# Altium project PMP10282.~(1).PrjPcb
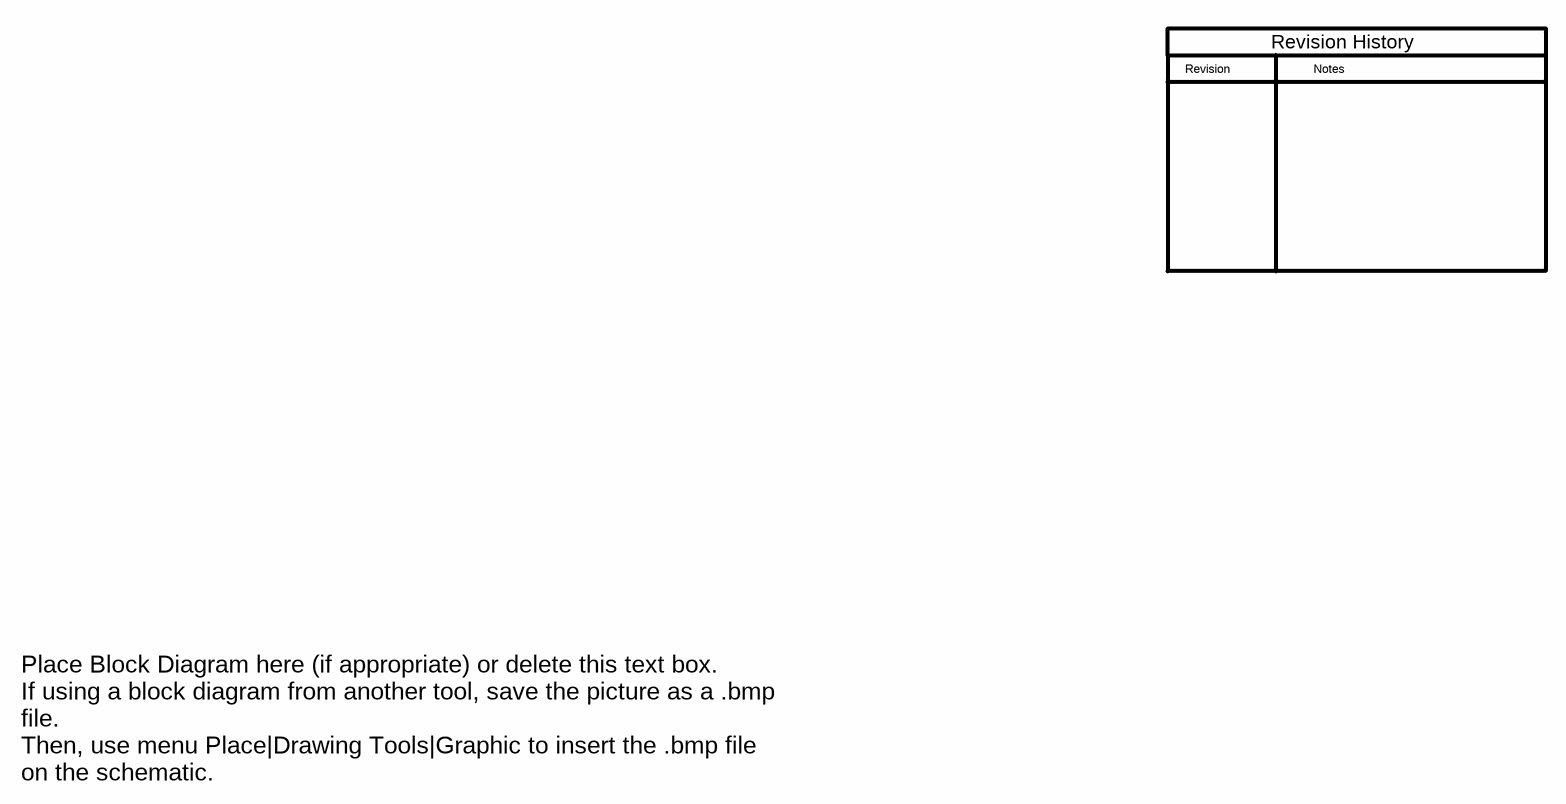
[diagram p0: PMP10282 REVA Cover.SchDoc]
CopyrightYear: 2014; PCB_Layout: Who did the Layout?; PCB_Rev: E1; PRJ_Customer: Public Release; PRJ_Engineer: Enter name of project lead; PRJ_Number: XX####; PRJ_Title: Change in menu Project|Project Options|Parameters; SCH_Rev: E1; TechSupport: http://www.ti.com/support
3 sheets, 79 parts. Net scope: global (net labels, ports and power ports of the same name join across sheets).
Board file: PMP10282 REVA.PcbDoc
Sheets:
  PMP10282 REVA Cover.SchDoc
  PMP10282 REVA.SchDoc
  PMP10282 REVA Hardware.SchDoc

## Sheet PMP10282 REVA Cover.SchDoc
size 431 x 279 mm; Date: Not shown in title block; ApprovedBy: Not shown in title block; CheckedBy: Not shown in title block; Author: Not shown in title block; CompanyName: Not shown in title block; Engineer: Not shown in title block; Organization: Not shown in title block; Address1: Not shown in title block; Address2: Not shown in title block; Address3: Not shown in title block; Address4: Not shown in title block; DocumentNumber: 1; Revision: Use project parameter SCH_Rev; SheetNumber: 1; SheetTotal: 1; PageSetup: Record=PageOptions|CenterHorizontal=True|CenterVertical=True|PrintScale=1.00|XCorrection=1.00|YCorrection=1.00|PrintKind=0|BorderSize=5000000|LeftOffset=0|BottomOffset=0|Orientation=2|PaperLength=1000|PaperWidth=1000|Scale=100|PaperSource=15|PrintQuality=600|MediaType=1|DitherType=10|PaperKind=Letter|PrintScaleMode=1

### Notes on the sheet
- Revision
- Notes
- Revision History
- Place Block Diagram here (if appropriate) or delete this text box.
  If using a block diagram from another tool, save the picture as a .bmp file.
  Then, use menu Place|Drawing Tools|Graphic to insert the .bmp file on the schematic.

## Sheet PMP10282 REVA.SchDoc
size 431 x 279 mm; Date: Not shown in title block; ApprovedBy: Not shown in title block; CheckedBy: Not shown in title block; Author: Not shown in title block; CompanyName: Not shown in title block; Engineer: Not shown in title block; Organization: Not shown in title block; Address1: Not shown in title block; Address2: Not shown in title block; Address3: Not shown in title block; Address4: Not shown in title block; DocumentNumber: 1; Revision: Use project parameter SCH_Rev; SheetNumber: 1; SheetTotal: 1; PageSetup: Record=PageOptions|CenterHorizontal=True|CenterVertical=True|PrintScale=1.00|XCorrection=1.00|YCorrection=1.00|PrintKind=0|BorderSize=5000000|LeftOffset=0|BottomOffset=0|Orientation=2|PaperLength=1000|PaperWidth=1000|Scale=100|PaperSource=15|PrintQuality=600|MediaType=1|DitherType=10|PaperKind=Letter|PrintScaleMode=1
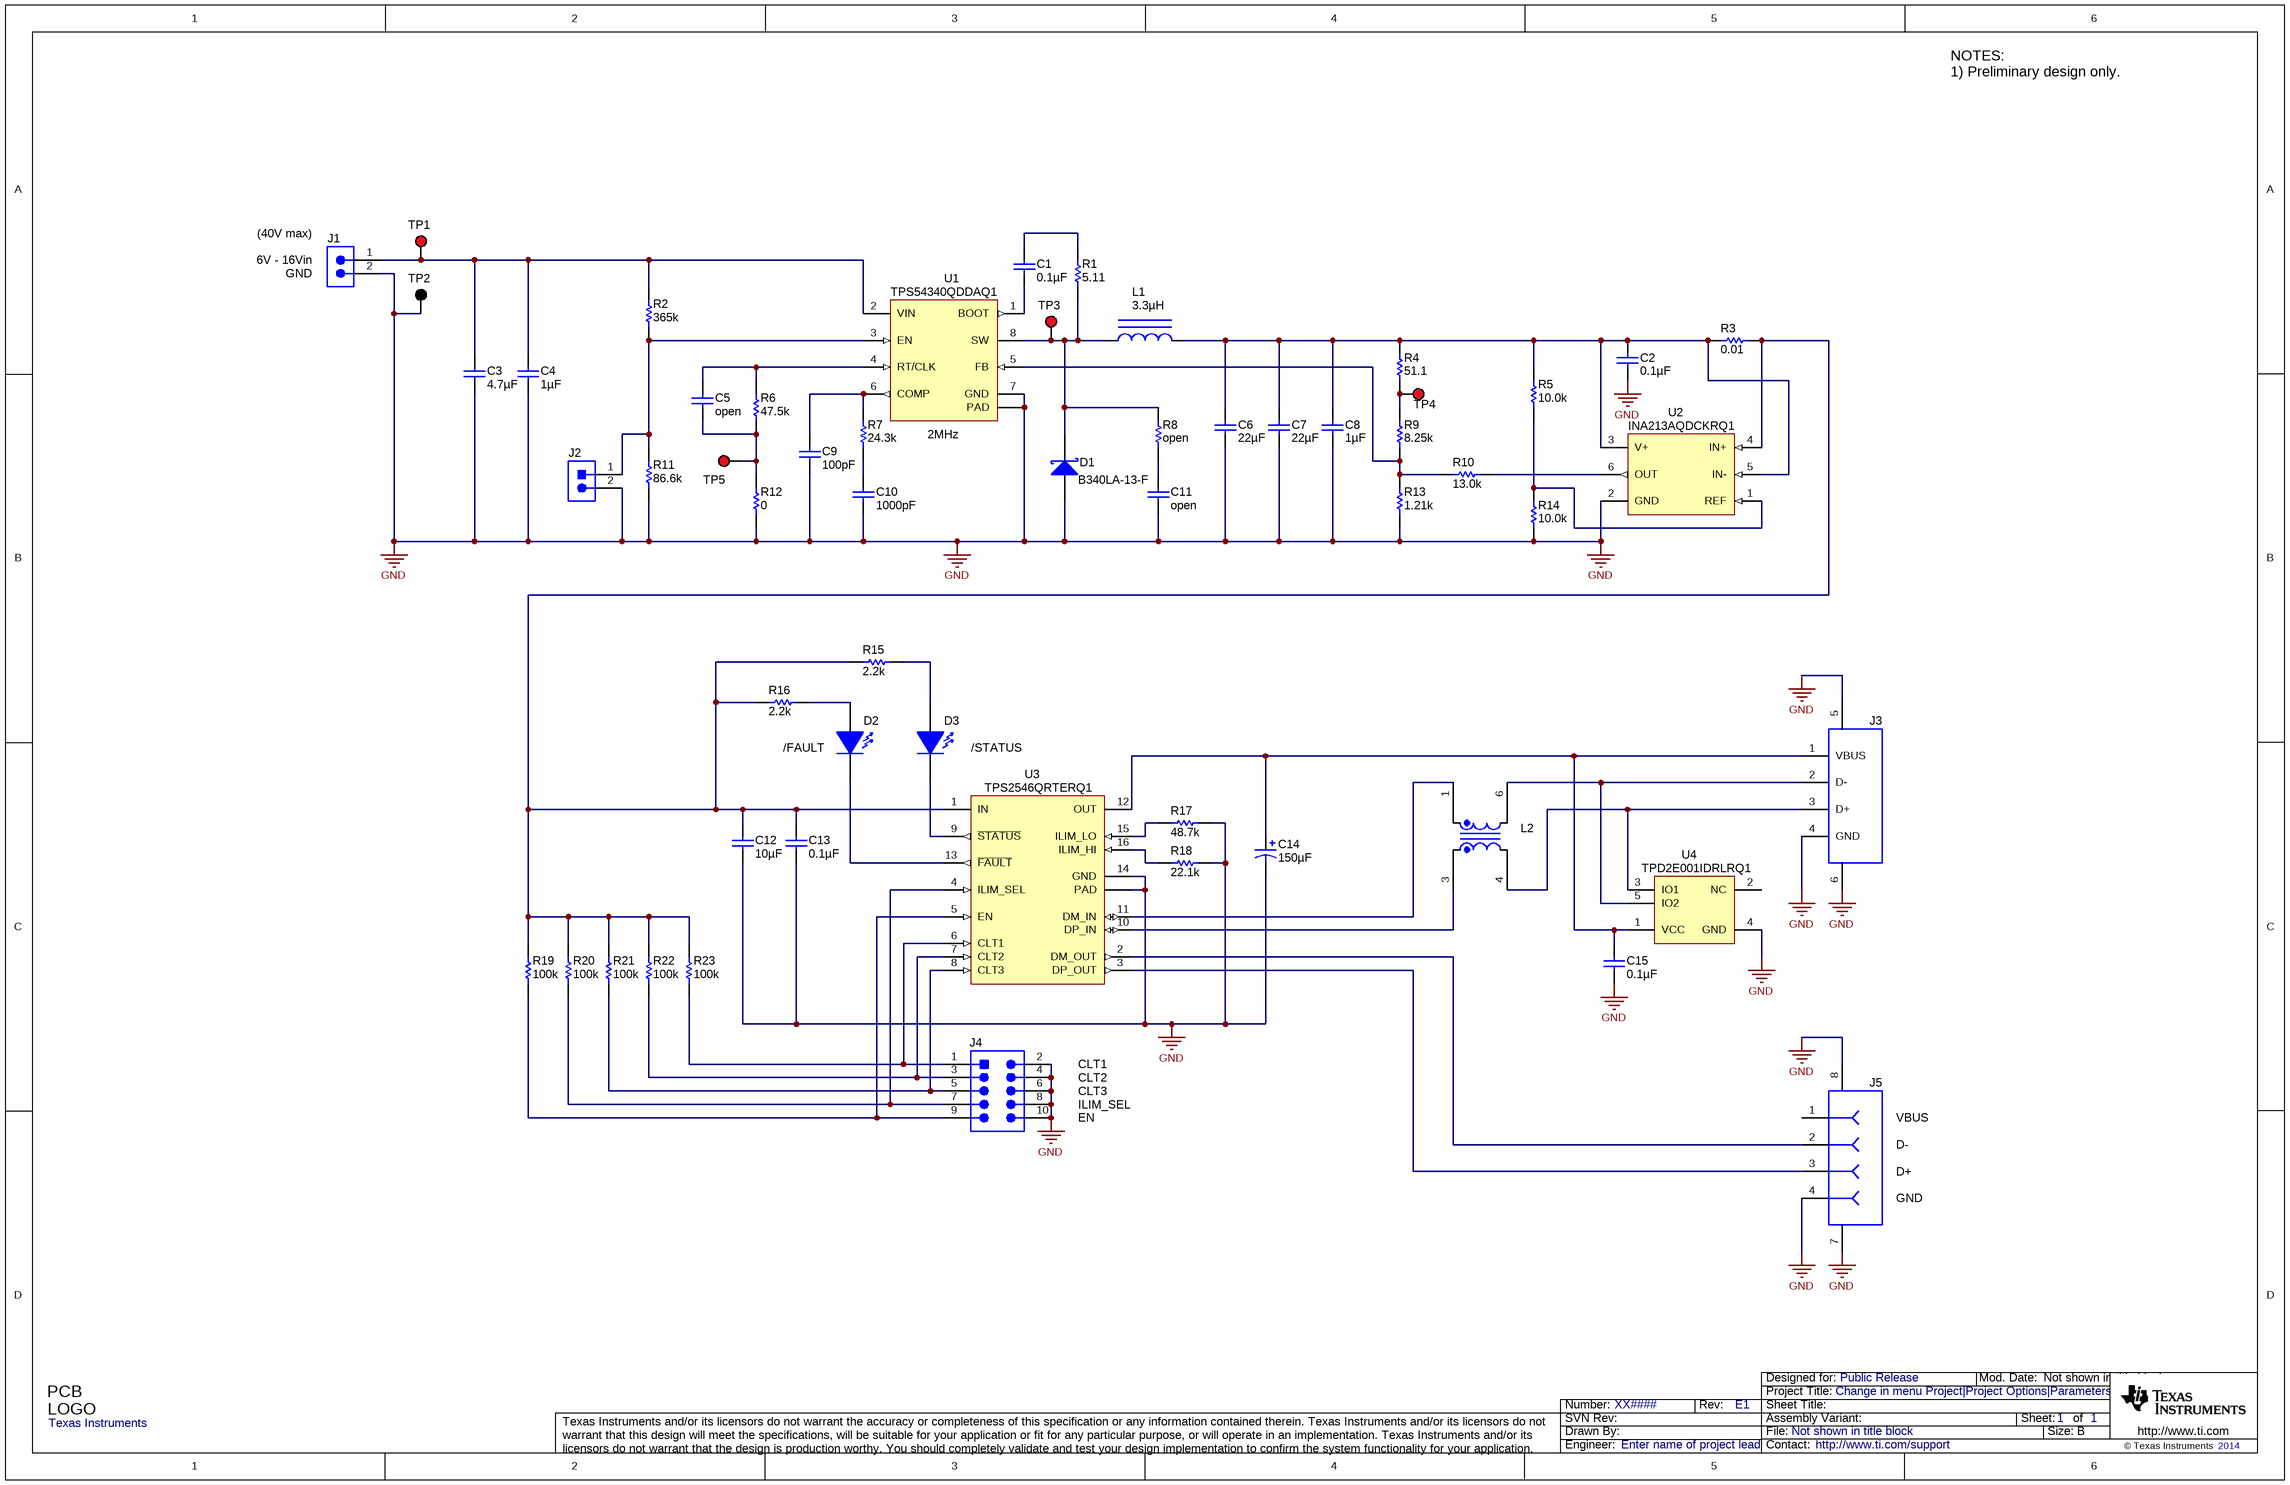
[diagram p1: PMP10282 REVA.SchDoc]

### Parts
C1  ValueDisplayed: 0.1µF  [0402]  (hidden comment: C1005X7R1H104K050BB)
C2  ValueDisplayed: 0.1µF  [0402]  (hidden comment: C1005X7R1H104K050BB)
C3  ValueDisplayed: 4.7µF  [1206]  (hidden comment: GRM31CR71H475KA12L)
C4  ValueDisplayed: 1µF  [0603]  (hidden comment: UMK107AB7105KA-T)
C5  ValueDisplayed: open  [0402]
C6  ValueDisplayed: 22µF  [0805_HV]  (hidden comment: GRM21BR61A226ME44)
C7  ValueDisplayed: 22µF  [0805_HV]  (hidden comment: GRM21BR61A226ME44)
C8  ValueDisplayed: 1µF  [0603]  (hidden comment: UMK107AB7105KA-T)
C9  ValueDisplayed: 100pF  [0402]  (hidden comment: GRM1535C1H101JDD5D)
C10  ValueDisplayed: 1000pF  [0402]  (hidden comment: C1005C0G1E102J)
C11  ValueDisplayed: open  [0402]
C12  ValueDisplayed: 10µF  [0805_HV]  (hidden comment: GRM21BR71A106KE51L)
C13  ValueDisplayed: 0.1µF  [0402]  (hidden comment: C1005X7R1H104K050BB)
C14  ValueDisplayed: 150µF  [TPB_D4]  (hidden comment: 10TPB150ML)
C15  ValueDisplayed: 0.1µF  [0402]  (hidden comment: C1005X7R1H104K050BB)
D1  B340LA-13-F  [SMA]
D2  value /FAULT  [LED_LTST-C190]  (hidden comment: LTST-C190GKT)
D3  value /STATUS  [LED_LTST-C190]  (hidden comment: LTST-C190GKT)
J1  ED555/2DS  [TERM_BLK_ED555-2DS]  (value not drawn)
J2  PEC02SAAN  [CONN_PEC02SAAN]  (value not drawn)
J3  676430910  [MOLEX_0676430910]  (value not drawn)
J4  PEC05DAAN  [CONN_PEC05DAAN]  (value not drawn)
J5  48037-1000  [CONN_USB-A-48037-1000]  (value not drawn)
L1  ValueDisplayed: 3.3µH  [SPM6530]  (hidden comment: SPM6530T-3R3M)
L2  985DH-1026  [NT2012]  (value not drawn)
Logo1  Texas Instruments  [TI_Stacked_Overlay_Small]  (no BOM)
R1  value 5.11  [0603]  (hidden comment: CRCW06035R11FKEA)
R2  value 365k  [0402]  (hidden comment: CRCW0402365KFKED)
R3  value 0.01  [2512M]  (hidden comment: ERJ-M1WSF10MU)
R4  value 51.1  [0402]  (hidden comment: CRCW040251R1FKED)
R5  value 10.0k  [0402]  (hidden comment: CRCW040210K0FKED)
R6  value 47.5k  [0402]  (hidden comment: CRCW040247K5FKED)
R7  value 24.3k  [0402]  (hidden comment: CRCW040224K3FKED)
R8  value open  [0805_HV]
R9  value 8.25k  [0402]  (hidden comment: CRCW04028K25FKED)
R10  value 13.0k  [0402]  (hidden comment: CRCW040213K0FKED)
R11  value 86.6k  [0402]  (hidden comment: CRCW040286K6FKED)
R12  value 0  [0402]  (hidden comment: CRCW04020000Z0ED)
R13  value 1.21k  [0402]  (hidden comment: CRCW04021K21FKED)
R14  value 10.0k  [0402]  (hidden comment: CRCW040210K0FKED)
R15  value 2.2k  [0402]  (hidden comment: CRCW04022K20JNED)
R16  value 2.2k  [0402]  (hidden comment: CRCW04022K20JNED)
R17  value 48.7k  [0402]  (hidden comment: CRCW040248K7FKED)
R18  value 22.1k  [0402]  (hidden comment: CRCW040222K1FKED)
R19  value 100k  [0402]  (hidden comment: CRCW0402100KFKED)
R20  value 100k  [0402]  (hidden comment: CRCW0402100KFKED)
R21  value 100k  [0402]  (hidden comment: CRCW0402100KFKED)
R22  value 100k  [0402]  (hidden comment: CRCW0402100KFKED)
R23  value 100k  [0402]  (hidden comment: CRCW0402100KFKED)
TP1  5000  [Keystone5000]  (value not drawn)
TP2  5001  [Keystone5001]  (value not drawn)
TP3  5010  [Keystone5010]  (value not drawn)
TP4  5010  [Keystone5010]  (value not drawn)
TP5  5010  [Keystone5010]  (value not drawn)
U1  TPS54340QDDAQ1  [DDA0008E_N]
U2  INA213AQDCKRQ1  [DCK0006A_N]
U3  TPS2546QRTERQ1  [RTE0016C]
U4  TPD2E001IDRLRQ1  [DRL0005A]

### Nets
GND: C2.2 C3.2 C4.2 C6.2 C7.2 C8.2 C9.2 C10.2 C11.2 C12.2 C13.2 C14.2(-) C15.2 D1.2(A) J1.2 J2.2 J3.4(GND) J3.5(Shield) J3.6(Shield) J4.2 J4.4 J4.6 J4.8 J4.10 J5.4 J5.7 J5.8 R11.1 R12.1 R13.1 R14.1 R17.1 R18.1 TP2.1 U1.7(GND) U1.9(PAD) U2.2(GND) U3.14(GND) U3.17(PAD) U4.4(GND)
NetC1_1: C1.1 R1.2
NetC1_2: C1.2 U1.1(BOOT)
NetC2_1: C2.1 C6.1 C7.1 C8.1 L1.2 R3.1 R4.2 R5.2 U2.3(V+) U2.5(IN-)
NetC3_1: C3.1 C4.1 J1.1 R2.2 TP1.1 U1.2(VIN)
NetC5_1: C5.1 R6.2 U1.4(RT/CLK)
NetC5_2: C5.2 R6.1 R12.2 TP5.1
NetC9_1: C9.1 R7.2 U1.6(COMP)
NetC10_1: C10.1 R7.1
NetC11_1: C11.1 R8.1
NetC12_1: C12.1 C13.1 R3.2 R15.2 R16.2 R19.2 R20.2 R21.2 R22.2 R23.2 U2.4(IN+) U3.1(IN)
NetC14_1: C14.1(+) C15.1 J3.1(VBUS) U3.12(OUT) U4.1(VCC)
NetD1_1: D1.1(K) L1.1 R1.1 R8.2 TP3.1 U1.8(SW)
NetD2_1: D2.1(A) R16.1
NetD2_2: D2.2(K) U3.13(~{FAULT})
NetD3_1: D3.1(A) R15.1
NetD3_2: D3.2(K) U3.9(~{STATUS})
NetJ2_1: J2.1 R2.1 R11.2 U1.3(EN)
NetJ3_2: J3.2(D-) L2.6 U4.5(IO2)
NetJ3_3: J3.3(D+) L2.4 U4.3(IO1)
NetJ4_1: J4.1 R23.1 U3.6(CLT1)
NetJ4_3: J4.3 R22.1 U3.7(CLT2)
NetJ4_5: J4.5 R21.1 U3.8(CLT3)
NetJ4_7: J4.7 R20.1 U3.4(ILIM_SEL)
NetJ4_9: J4.9 R19.1 U3.5(EN)
NetJ5_2: J5.2 U3.2(DM_OUT)
NetJ5_3: J5.3 U3.3(DP_OUT)
NetL2_1: L2.1 U3.11(DM_IN)
NetL2_3: L2.3 U3.10(DP_IN)
NetR4_1: R4.1 R9.2 TP4.1
NetR5_1: R5.1 R14.2 U2.1(REF)
NetR9_1: R9.1 R10.2 R13.2 U1.5(FB)
NetR10_1: R10.1 U2.6(OUT)
NetR17_2: R17.2 U3.15(ILIM_LO)
NetR18_2: R18.2 U3.16(ILIM_HI)

Not connected (* = marked no-connect by the designer): J5 1; U4 2(NC)

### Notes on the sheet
- NOTES:
  1) Preliminary design only.
- (near J1) (40V max)
- (near J1) 6V - 16Vin
- (near J1) GND
- (near U1) 2MHz
- CLT1
- CLT2
- CLT3
- ILIM_SEL
- EN
- VBUS
- D-
- D+
- GND

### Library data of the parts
C1 C2 C13 C15 = C1005X7R1H104K050BB: CAP, CERM, 0.1uF, 50V, +/-10%, X7R, 0402; Manufacturer: TDK; Polarized: N; CompType: Capacitor; U/M: EA; Cap_F: 0.0000001; Tolerance_%: 10; Value1: Unknown; VDC_V: 50; TaMin_C: -55; TaMax_C: 125
C3 = GRM31CR71H475KA12L: CAP, CERM, 4.7uF, 50V, +/-10%, X7R, 1206; Manufacturer: MuRata; Polarized: N; CompType: Capacitor; U/M: EA; Cap_F: 0.0000047; Tolerance_%: 10; Value1: Unknown; VDC_V: 50; TaMin_C: -55; TaMax_C: 125; Cap_Case: 2220
C4 C8 = UMK107AB7105KA-T: CAP, CERM, 1uF, 50V, +/-10%, X7R, 0603; Manufacturer: Taiyo Yuden; Polarized: N; CompType: Capacitor; U/M: EA; Cap_F: 0.000001; Tolerance_%: 10; Value1: Unknown; VDC_V: 50; TaMin_C: -55; TaMax_C: 125
C5 = C1005X7R1H104K050BB: CAP, open, 0402; Polarized: N; CompType: Capacitor; U/M: EA; Cap_F: 0.0000001; Tolerance_%: 10; Value1: Unknown; TaMin_C: -55; TaMax_C: 125
C6 C7 = GRM21BR61A226ME44: CAP, CERM, 22uF, 10V, +/-20%, X5R, 0805; Manufacturer: MuRata; Polarized: N; CompType: Capacitor; U/M: EA; Cap_F: 0.000022; Tolerance_%: 20; Value1: Unknown; VDC_V: 10; TaMin_C: -55; TaMax_C: 85; Cap_Case: 0805
C9 = GRM1535C1H101JDD5D: CAP, CERM, 100pF, 50V, +/-5%, C0G/NP0, 0402; Manufacturer: MuRata; Polarized: N; CompType: Capacitor; U/M: EA; Cap_F: 0.0000000001; Tolerance_%: 5; Value1: Unknown; VDC_V: 50; TaMin_C: -55; TaMax_C: 125
C10 = C1005C0G1E102J: CAP, CERM, 1000pF, 25V, +/-5%, C0G/NP0, 0402; Manufacturer: TDK; Polarized: N; CompType: Capacitor; U/M: EA; Cap_F: 0.000000001; Tolerance_%: 5; Value1: Unknown; VDC_V: 25; TaMin_C: -55; TaMax_C: 125
C11 = C1005C0G1E102J: CAP, open, 0402; Polarized: N; CompType: Capacitor; U/M: EA; Cap_F: 0.000000001; Tolerance_%: 5; Value1: Unknown; TempCo: C0G/NP0; TaMin_C: -55; TaMax_C: 125
C12 = GRM21BR71A106KE51L: CAP, CERM, 10uF, 10V, +/-10%, X7R, 0805; Manufacturer: MuRata; Polarized: N; CompType: Capacitor; U/M: EA; Cap_F: 0.00001; Tolerance_%: 10; ESR_Ohm: 0.003; Value1: 0.003 ohm; TaMin_C: -55; TaMax_C: 125; Cap_Case: 0805
C14 = 10TPB220M: CAP, 150uF, 10V, +/-20%, 0.04 ohm, SMD; Manufacturer: Panasonic; Polarized: Y; CompType: Capacitor; U/M: EA; Cap_F: 0.00022; Tolerance_%: 20; VDC_V: 10; ESR_Ohm: 0.04; IRMS_A: 3; TaMin_C: -55; TaMax_C: 105; Cap_Case: D
D1 = B340LA-13-F: Diode, Schottky, 40V, 3A, SMA; Manufacturer: Diodes Inc.; U/M: EA; Vf_V: 0.45; Value2: 0.45V; Io_A: 3; Vr_V: 40; TJmax_C: 125; RJC_CperW: 25
D2 D3 = LTST-C190GKT: LED, Green, SMD; Manufacturer: Lite-On; Vf_V: 2.1; Value2: 2.1V; Io_A: 0.02; Power_TotalModule: 0.1; Value1: 0.1W; U/M: EA
J1 = ED555/2DS: Terminal Block, 6A, 3.5mm Pitch, 2-Pos, TH; Manufacturer: On-Shore Technology, Inc.; SymbolCreator: a0412235; CompType: Connector; U/M: EA
J2 = PEC02SAAN: Header, 100mil, 2x1, Tin, TH; Manufacturer: Sullins Connector Solutions; SymbolCreator: a0412235; U/M: EA
J3 = 676430910: Connector, Receptacle, USB Standard, R/A, Top Mount TH; Manufacturer: Molex; SymbolCreator: a0412235; U/M: EA
J4 = PEC05DAAN: Header, 100mil, 5x2, Tin plated, TH; Manufacturer: Sullins Connector Solutions; SymbolCreator: a0412235; U/M: EA
J5 = 48037-1000: Connector, Plug, USB Type A, R/A, Top Mount SMT; Manufacturer: Molex; SymbolCreator: a0412235; U/M: EA
L1 = SPM6530T-3R3M: Inductor, Shielded, Ferrite, 3.3uH, 6.8A, 0.0297 ohm, SMD; Manufacturer: TDK; Ind_H: 3.3E-6; Imax_A: 6.8; Irms: 6.8A @ 40C rise; Isat: 7.3A @ 20% inductance drop; DCR_ohm: 0.0297
L2 = 985DH-1023: Coupled inductor, 0.28A, 0.36 ohm, SMD; Manufacturer: Toko; SymbolCreator: a0411947; DCR_ohm: 0.21; Isat: 0.37
Logo1 = TI_Logo: Texas Instrument Corporate Signature; SymbolCreator: a0412235
R1 = CRCW06035R11FKEA: RES, 5.11 ohm, 1%, 0.1W, 0603; Manufacturer: Vishay-Dale; CompType: Resistor; Value_Code: 5R11; Tolerance_%: 1; Power_W: 0.1; VDC_V: 75; TempCo: 100 ppm/C; EIA_Code: E96; U/M: EA
R2 = CRCW0402365KFKED: RES, 365k ohm, 1%, 0.063W, 0402; Manufacturer: Vishay-Dale; CompType: Resistor; Res_ohm: 365000; Tolerance_%: 1; Power_W: 0.063; VDC_V: 50; TempCo: 100 ppm/C; EIA_Code: E96; U/M: EA
R3 = ERJ-M1WSF10MU: RES, 0.01 ohm, 1%, 1W, 2512; Manufacturer: Panasonic; CompType: Resistor; Value_Code: R010; Tolerance_%: 1; TempCo: 100 ppm/C; EIA_Code: E96; U/M: EA
R4 = CRCW040251R1FKED: RES, 51.1 ohm, 1%, 0.063W, 0402; Manufacturer: Vishay-Dale; CompType: Resistor; Value_Code: 51R1; Tolerance_%: 1; Power_W: 0.063; VDC_V: 50; TempCo: 100 ppm/C; EIA_Code: E96; U/M: EA
R5 R14 = CRCW040210K0FKED: RES, 10.0k ohm, 1%, 0.063W, 0402; Manufacturer: Vishay-Dale; CompType: Resistor; Res_ohm: 10000; Value_Code: 10k0; Tolerance_%: 1; Power_W: 0.063; VDC_V: 50; TempCo: 100 ppm/C; EIA_Code: E96; U/M: EA
R6 = CRCW040247K5FKED: RES, 47.5k ohm, 1%, 0.063W, 0402; Manufacturer: Vishay-Dale; CompType: Resistor; Res_ohm: 47500; Value_Code: 47k5; Tolerance_%: 1; Power_W: 0.063; VDC_V: 50; TempCo: 100 ppm/C; EIA_Code: E96; U/M: EA
R7 = CRCW040224K3FKED: RES, 24.3k ohm, 1%, 0.063W, 0402; Manufacturer: Vishay-Dale; CompType: Resistor; Res_ohm: 24300; Value_Code: 24k3; Tolerance_%: 1; Power_W: 0.063; VDC_V: 50; TempCo: 100 ppm/C; EIA_Code: E96; U/M: EA
R8 = CRCW08051K78FKEA: RES, open, 0805; CompType: Resistor; Res_ohm: 1780; Tolerance_%: 1; Power_W: 0.125; TempCo: 100 ppm/C; EIA_Code: E96; U/M: EA
R9 = CRCW04028K25FKED: RES, 8.25k ohm, 1%, 0.063W, 0402; Manufacturer: Vishay-Dale; CompType: Resistor; Res_ohm: 8250; Value_Code: 8k25; Tolerance_%: 1; Power_W: 0.063; VDC_V: 50; TempCo: 100 ppm/C; EIA_Code: E96; U/M: EA
R10 = CRCW040213K0FKED: RES, 13.0k ohm, 1%, 0.063W, 0402; Manufacturer: Vishay-Dale; CompType: Resistor; Res_ohm: 13000; Value_Code: 13k0; Tolerance_%: 1; Power_W: 0.063; VDC_V: 50; TempCo: 100 ppm/C; EIA_Code: E96; U/M: EA
R11 = CRCW040286K6FKED: RES, 86.6k ohm, 1%, 0.063W, 0402; Manufacturer: Vishay-Dale; CompType: Resistor; Res_ohm: 86600; Value_Code: 86k6; Tolerance_%: 1; Power_W: 0.063; VDC_V: 50; TempCo: 100 ppm/C; EIA_Code: E96; U/M: EA
R12 = CRCW04020000Z0ED: RES, 0 ohm, 5%, 0.063W, 0402; Manufacturer: Vishay-Dale; CompType: Resistor; Value_Code: 0000; Tolerance_%: 5; Power_W: 0.063; VDC_V: 50; TempCo: 200 ppm/C; EIA_Code: E24; U/M: EA
R13 = CRCW04021K21FKED: RES, 1.21k ohm, 1%, 0.063W, 0402; Manufacturer: Vishay-Dale; CompType: Resistor; Res_ohm: 1210; Value_Code: 1k21; Tolerance_%: 1; Power_W: 0.063; VDC_V: 50; TempCo: 100 ppm/C; EIA_Code: E96; U/M: EA
R15 R16 = CRCW04022K20JNED: RES, 2.2k ohm, 5%, 0.063W, 0402; Manufacturer: Vishay-Dale; CompType: Resistor; Res_ohm: 2200; Value_Code: 2k20; Tolerance_%: 5; Power_W: 0.063; VDC_V: 50; TempCo: 200 ppm/C; EIA_Code: E24; U/M: EA
R17 = CRCW040248K7FKED: RES, 48.7k ohm, 1%, 0.063W, 0402; Manufacturer: Vishay-Dale; CompType: Resistor; Res_ohm: 48700; Value_Code: 48k7; Tolerance_%: 1; Power_W: 0.063; VDC_V: 50; TempCo: 100 ppm/C; EIA_Code: E96; U/M: EA
R18 = CRCW040222K1FKED: RES, 22.1k ohm, 1%, 0.063W, 0402; Manufacturer: Vishay-Dale; CompType: Resistor; Res_ohm: 22100; Value_Code: 22k1; Tolerance_%: 1; Power_W: 0.063; VDC_V: 50; TempCo: 100 ppm/C; EIA_Code: E96; U/M: EA
R19-R23 = CRCW0402100KFKED: RES, 100k ohm, 1%, 0.063W, 0402; Manufacturer: Vishay-Dale; CompType: Resistor; Res_ohm: 100000; Tolerance_%: 1; Power_W: 0.063; VDC_V: 50; TempCo: 100 ppm/C; EIA_Code: E96; U/M: EA
TP1 = 5000: Test Point, TH, Miniature, Red; Manufacturer: Keystone; CompType: Test Point Loop; U/M: EA
TP2 = 5001: Test Point, TH, Miniature, Black; Manufacturer: Keystone; CompType: Test Point Loop; U/M: EA
TP3-TP5 = 5010: Test Point, Multipurpose, Red, TH; Manufacturer: Keystone; CompType: Test Point Loop; U/M: EA
U1 = TPS54340DDA: 42 V Input, 3.5 A, Step Down DC-DC Converter with Eco-mode, DDA0008E; Alternate Manufacturer: None; Manufacturer: Texas Instruments; SymbolCreator: a0411947; CompType: IC; U/M: EA
U2 = INA213AIDCK: Voltage Output, High or Low Side Measurement, Bi-Directional Zero-Drift Series Current-Shunt Monitor, DCK0006A; Alternate Manufacturer: None; Manufacturer: Texas Instruments; SymbolCreator: a0411947; CompType: IC; U/M: EA
U3 = TPS2546RTE: USB Charging Port Controller and Power Switch with Load Detection, RTE0016C; Alternate Manufacturer: None; Manufacturer: Texas Instruments; SymbolCreator: a0411947; CompType: IC; U/M: EA
U4 = TPD2E001IDRLRQ1: Automotive Catalog Low-Capacitance + / - 15 kV ESD-Protection Array for High-Speed Data Inter, 2 Channels, -40 to +85 degC, 5-pin SOT (DRL), Green (RoHS & no Sb/Br); Manufacturer: Texas Instruments; Alternate Manufacturer: None; Alternate PartNumber: Equivalent; Breakdown Voltage(Min)(V): 11; IEC 61000-4-2 Air-Gap(+/- kV): 15; IEC 61000-4-2 Contact(+/- kV): 8; IO Capacitance(Typ)(pF): 1.5; IO Leakage Current(nA): 1; SubFamily: ESD Solution; USB High Speed: TRUE

## Sheet PMP10282 REVA Hardware.SchDoc
size 431 x 279 mm; Date: Not shown in title block; ApprovedBy: Not shown in title block; CheckedBy: Not shown in title block; Author: Not shown in title block; CompanyName: Not shown in title block; Engineer: Not shown in title block; Organization: Not shown in title block; Address1: Not shown in title block; Address2: Not shown in title block; Address3: Not shown in title block; Address4: Not shown in title block; DocumentNumber: 1; Revision: Use project parameter SCH_Rev; SheetNumber: 1; SheetTotal: 1; PageSetup: Record=PageOptions|CenterHorizontal=True|CenterVertical=True|PrintScale=1.00|XCorrection=1.00|YCorrection=1.00|PrintKind=0|BorderSize=5000000|LeftOffset=0|BottomOffset=0|Orientation=2|PaperLength=1000|PaperWidth=1000|Scale=100|PaperSource=15|PrintQuality=600|MediaType=1|DitherType=10|PaperKind=Letter|PrintScaleMode=1
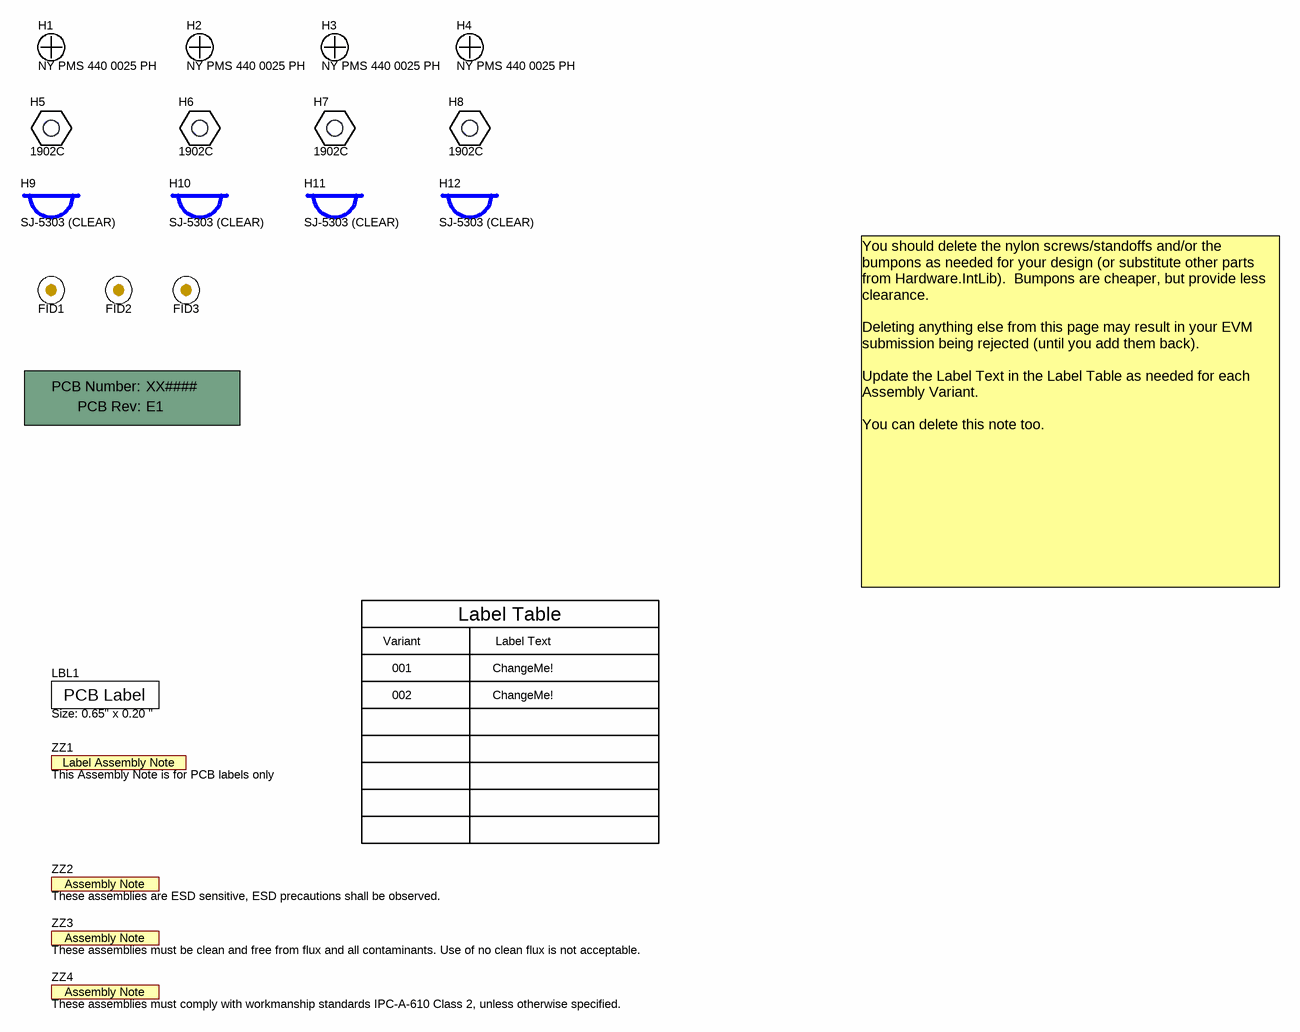
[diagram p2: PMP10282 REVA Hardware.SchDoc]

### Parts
!PCB  Printed Circuit Board  (value not drawn)  (mechanical)
FID1  Fiducial  [Fiducial10-20]  (value not drawn)
FID2  Fiducial  [Fiducial10-20]  (value not drawn)
FID3  Fiducial  [Fiducial10-20]  (value not drawn)
H1  NY PMS 440 0025 PH  [NY PMS 440 0025 PH]
H2  NY PMS 440 0025 PH  [NY PMS 440 0025 PH]
H3  NY PMS 440 0025 PH  [NY PMS 440 0025 PH]
H4  NY PMS 440 0025 PH  [NY PMS 440 0025 PH]
H5  1902C  [Keystone_1902C]
H6  1902C  [Keystone_1902C]
H7  1902C  [Keystone_1902C]
H8  1902C  [Keystone_1902C]
H9  SJ-5303 (CLEAR)  [Bumpon_SJ5003Transparent]
H10  SJ-5303 (CLEAR)  [Bumpon_SJ5003Transparent]
H11  SJ-5303 (CLEAR)  [Bumpon_SJ5003Transparent]
H12  SJ-5303 (CLEAR)  [Bumpon_SJ5003Transparent]
LBL1  Size: 0.65" x 0.20 "  [Label_650x200]
ZZ1  This Assembly Note is for PCB labels only  [AssemblyNoteLabel]  (no BOM)
ZZ2  These assemblies are ESD sensitive, ESD precautions shall be observed.  [AssemblyNote]  (no BOM)
ZZ3  These assemblies must be clean and free from flux and all contaminants. Use of no clean flux is not acceptable.  [AssemblyNote]  (no BOM)
ZZ4  These assemblies must comply with workmanship standards IPC-A-610 Class 2, unless otherwise specified.  [AssemblyNote]  (no BOM)

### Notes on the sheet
- Variant
- Label Table
- Label Text
- You should delete the nylon screws/standoffs and/or the bumpons as needed for your design (or substitute other parts from Hardware.IntLib).  Bumpons are cheaper, but provide less clearance.
  Deleting anything else from this page may result in your EVM submission being rejected (until you add them back).
  Update the Label Text in the Label Table as needed for each Assembly Variant.
  You can delete this note too.
- 001
- 002
- ChangeMe!

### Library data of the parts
!PCB = PCB: Manufacturer: Any; PartNumber: XX####; SymbolCreator: a0412235
FID1-FID3 = Fiducial: Fiducial mark.  There is nothing to buy or mount.; SymbolCreator: codlsc
H1-H4 = NY PMS 440 0025 PH: Machine Screw, Round, #4-40 x 1/4, Nylon, Philips panhead; Manufacturer: B&F Fastener Supply; CompType: Hardware; SymbolCreator: codlsc; U/M: EA
H5-H8 = 1902C: Standoff, Hex, 0.5"L #4-40 Nylon; Manufacturer: Keystone; CompType: Hardware; SymbolCreator: a0412235
H9-H12 = SJ-5303 (CLEAR): Bumpon, Hemisphere, 0.44 X 0.20, Clear; Manufacturer: 3M; SymbolCreator: a0412235
LBL1 = THT-14-423-10: Thermal Transfer Printable Labels, 0.650" W x 0.200" H - 10,000 per roll; Manufacturer: Brady; SymbolCreator: a0412235; CompType: Label
ZZ1 = AssemblyNoteLabel: SymbolCreator: a0412235
ZZ2-ZZ4 = AssemblyNote: SymbolCreator: codlsc

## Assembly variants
001: not fitted FID1 FID2 FID3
